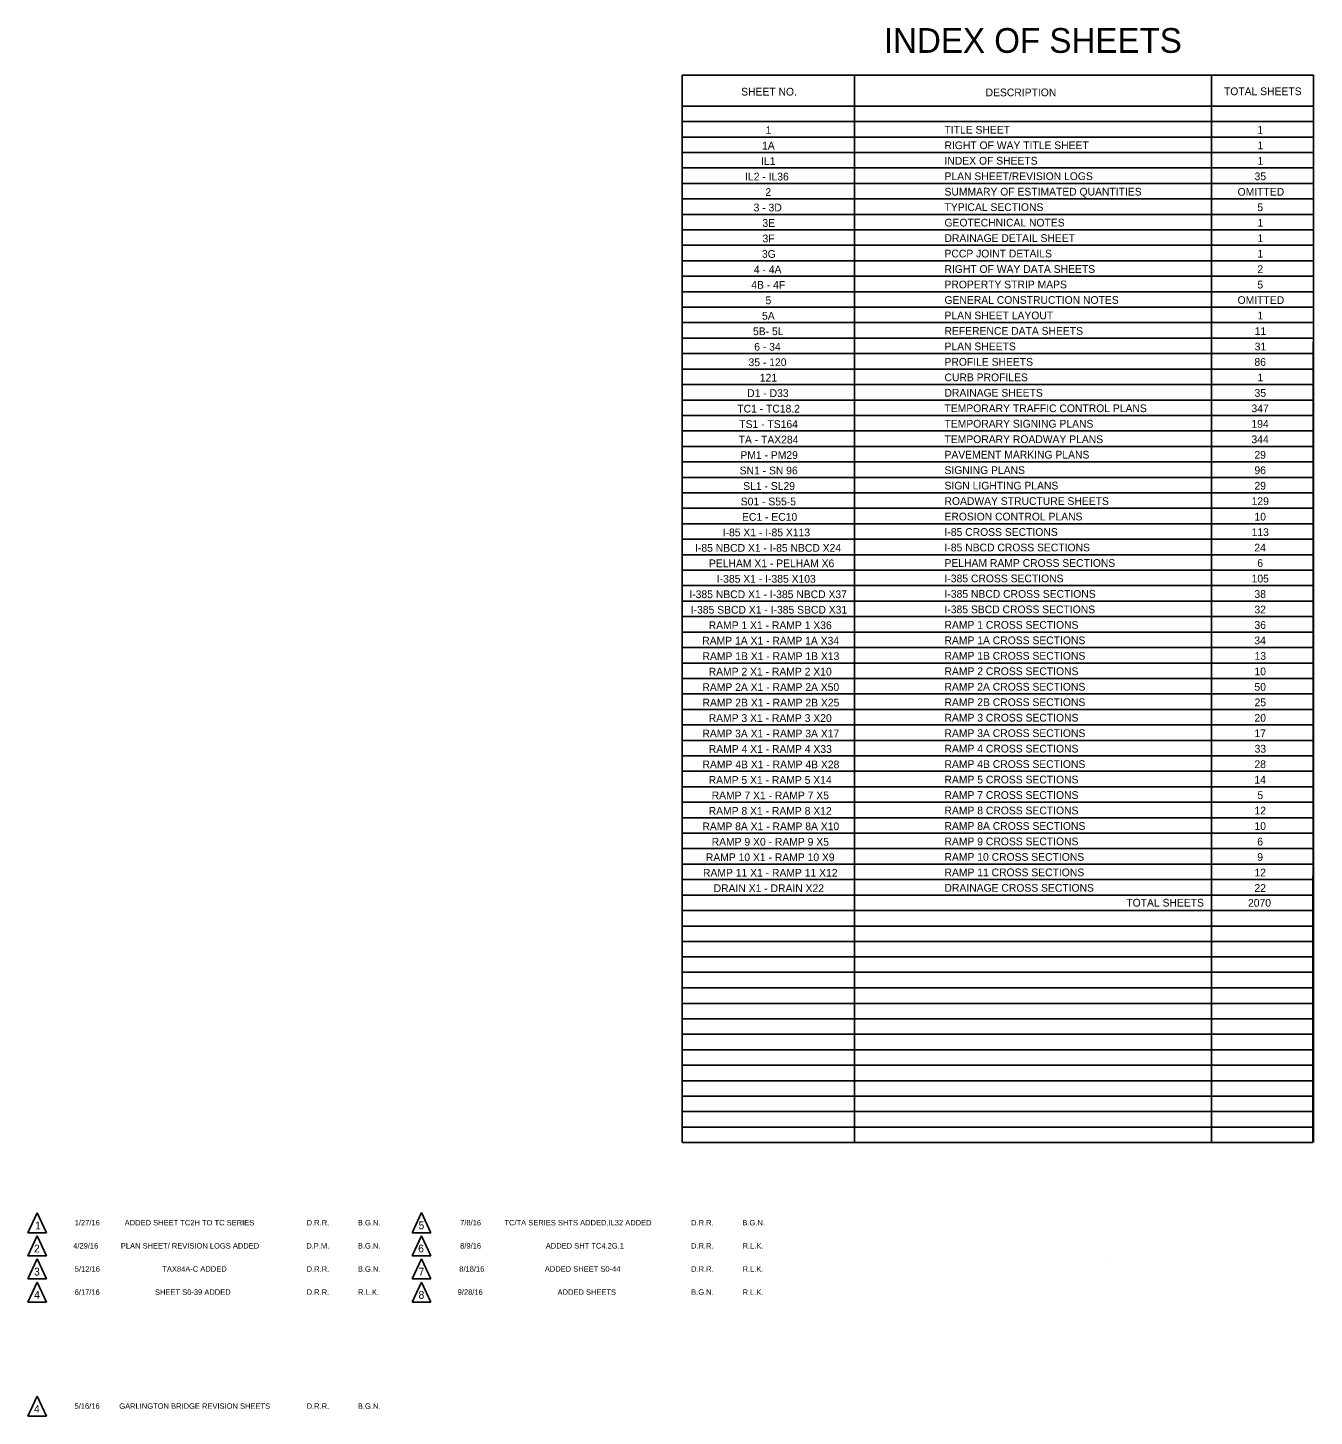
# Model space of a CAD drawing. Extents: x 116 to 2310, y 9 to 1131.
# Drawn here: x 116 to 1155, y 9 to 1131 of the extents above; entities that cross this region are included whole.
import ezdxf

# ---------------------------------------------------------------- set-up
doc = ezdxf.new("R2010")
doc.units = 0
for name, color, linetype in [('BR_AUTO DIMENSION', 7, 'Continuous'), ('BR_TEXT', 7, 'Continuous'), ('Level 3', 7, 'Continuous'), ('Level 6', 7, 'Continuous'), ('RD_SHT_Bndy', 7, 'Continuous'), ('RD_SHT_TX', 7, 'Continuous')]:
    doc.layers.add(name, color=color, linetype=linetype)

msp = doc.modelspace()

# ---------------------------------------------------------------- linework, layer by layer
at = {"layer": 'BR_AUTO DIMENSION'}
for p, q in [((123.7, 173.2), (116.2, 157)), ((123.7, 173.2), (131.2, 157)), ((434.3, 173.3), (426.8, 157.1)), ((434.3, 173.3), (441.8, 157.1)), ((116.2, 157), (131.2, 157)), ((123.7, 154.6), (116.2, 138.4)), ((123.7, 154.6), (131.2, 138.4)), ((426.8, 157.1), (441.8, 157.1)), ((434.3, 154.6), (426.8, 138.4)), ((434.3, 154.6), (441.8, 138.4)), ((116.2, 138.4), (131.2, 138.4)), ((123.7, 135.9), (116.2, 119.7)), ((123.7, 135.9), (131.2, 119.7)), ((426.8, 138.4), (441.8, 138.4)), ((434.3, 135.9), (426.8, 119.7)), ((434.3, 135.9), (441.8, 119.7)), ((116.2, 119.7), (131.2, 119.7)), ((123.7, 117.2), (116.2, 101)), ((123.7, 117.2), (131.2, 101)), ((426.8, 119.7), (441.8, 119.7)), ((434.3, 117.2), (426.8, 101)), ((434.3, 117.2), (441.8, 101)), ((116.2, 101), (131.2, 101)), ((426.8, 101), (441.8, 101)), ((123.7, 25), (116.2, 8.8)), ((123.7, 25), (131.2, 8.8)), ((116.2, 8.8), (131.2, 8.8))]:
    msp.add_line(p, q, dxfattribs=at)
at = {"layer": 'Level 3'}
msp.add_line((987.4, 136), (987.4, 136), dxfattribs=at)
msp.add_line((987.4, 136), (987.4, 136), dxfattribs=at)
at = {"layer": 'RD_SHT_Bndy'}
for p, q in [((644.9, 1092.4), (1154.9, 1092.4)), ((644.9, 1092.4), (644.9, 229.9)), ((784.1, 1092.4), (784.1, 229.9)), ((1072.5, 1092.4), (1072.5, 229.9)), ((1154.9, 1092.4), (1154.3, 229.9)), ((1154.9, 1092.4), (1154.9, 229.9)), ((644.9, 1067.4), (1154.4, 1067.4)), ((645.2, 1054.9), (1154.4, 1054.9)), ((645.2, 1042.4), (1154.4, 1042.4)), ((645.2, 1029.9), (1154.7, 1029.9)), ((645.2, 1017.4), (1154.7, 1017.4)), ((645.2, 1004.9), (1154.7, 1004.9)), ((645.2, 992.4), (1154.4, 992.4)), ((645.2, 979.9), (1154.4, 979.9)), ((645.2, 967.4), (1154.4, 967.4)), ((645.2, 954.9), (1154.7, 954.9)), ((645.2, 942.4), (1154.4, 942.4)), ((645.2, 929.9), (1154.7, 929.9)), ((645.2, 917.4), (1154, 917.4)), ((645.2, 904.9), (1154.2, 904.9)), ((645.2, 892.4), (1154.7, 892.4)), ((645.2, 879.9), (1154.5, 879.9)), ((645.2, 867.4), (1154.7, 867.4)), ((645.2, 854.9), (1154.5, 854.9)), ((645.2, 842.4), (1154.2, 842.4)), ((645.2, 829.9), (1155.5, 829.9)), ((645.2, 817.4), (1154.5, 817.4)), ((645.2, 804.9), (1154.5, 804.9)), ((645.2, 792.4), (1154.5, 792.4)), ((645.2, 779.9), (1154.5, 779.9)), ((645.2, 767.4), (1154.8, 767.4)), ((645.2, 754.9), (1154.5, 754.9)), ((645.2, 742.4), (1154.5, 742.4)), ((645.2, 729.9), (1154.5, 729.9)), ((645.2, 717.4), (1155.3, 717.4)), ((645.2, 704.9), (1154.5, 704.9)), ((645.2, 692.4), (1154.5, 692.4)), ((645.2, 679.9), (1154.8, 679.9)), ((645.2, 667.4), (1154.8, 667.4)), ((645.2, 654.9), (1154.5, 654.9)), ((645.2, 642.4), (1154.3, 642.4)), ((645.2, 629.9), (1154, 629.9)), ((645.2, 617.4), (1154.3, 617.4)), ((645.2, 604.9), (1154.8, 604.9)), ((645.2, 592.4), (1154.7, 592.4)), ((645.2, 579.9), (1154.2, 579.9)), ((645.2, 567.4), (1154, 567.4)), ((645.2, 554.9), (1154.7, 554.9)), ((645.2, 542.4), (1154.5, 542.4)), ((645.2, 529.9), (1154.7, 529.9)), ((645.2, 517.4), (1154.5, 517.4)), ((645.2, 504.9), (1154.7, 504.9)), ((645.2, 492.4), (1154.7, 492.4)), ((645.2, 479.9), (1154.5, 479.9)), ((645.2, 467.4), (1154.5, 467.4)), ((645.2, 454.9), (1154.5, 454.9)), ((645.2, 442.4), (1154.7, 442.4)), ((645.2, 429.9), (1154.7, 429.9)), ((645.2, 417.4), (1154.3, 417.4)), ((645.2, 404.9), (1154.1, 404.9)), ((645.2, 392.4), (1154.1, 392.4)), ((645.2, 379.9), (1154.8, 379.9)), ((645.2, 367.5), (1154.1, 367.5)), ((645.2, 354.9), (1154.1, 354.9)), ((645.2, 342.4), (1154.3, 342.4)), ((645.2, 329.9), (1154.1, 329.9)), ((645.2, 317.4), (1154.3, 317.4)), ((645.2, 304.9), (1154.6, 304.9)), ((645.2, 292.4), (1154.6, 292.4)), ((645.2, 279.9), (1154.3, 279.9)), ((645.2, 267.4), (1154.3, 267.4)), ((645.2, 254.9), (1154.3, 254.9)), ((645.2, 242.4), (1154.3, 242.4)), ((645.2, 229.9), (1154.3, 229.9))]:
    msp.add_line(p, q, dxfattribs=at)

# ---------------------------------------------------------------- texts
at = {"layer": 'BR_TEXT'}
for s, p in [('1', (122.1, 159.8)), ('5', (431.9, 159.9)), ('2', (121.2, 141.2)), ('6', (431.6, 141.2)), ('3', (121.3, 122.5)), ('7', (431.9, 122.5)), ('4', (121.3, 103.8)), ('8', (431.9, 103.7)), ('4', (121.2, 11.6))]:
    msp.add_text(s, height=6.25, dxfattribs=at).set_placement(p)
at = {"layer": 'Level 6'}
msp.add_text('INDEX OF SHEETS', height=20, dxfattribs=at).set_placement((807.8, 1110.4))
at = {"layer": 'RD_SHT_TX'}
for s, height, p in [('SHEET NO.', 6.25, (692.5, 1075.9)), ('DESCRIPTION', 6.25, (890, 1075.3)), ('TOTAL SHEETS', 6.25, (1082.6, 1076.2)), ('1', 6.25, (712.3, 1044.8)), ('TITLE SHEET', 6.25, (856.8, 1045.1)), ('1', 6.25, (1109.7, 1045)), ('1A', 6.25, (709.4, 1032.3)), ('RIGHT OF WAY TITLE SHEET', 6.25, (856.8, 1032.6)), ('1', 6.25, (1109.7, 1032.5)), ('IL1', 6.25, (708.6, 1019.8)), ('INDEX OF SHEETS', 6.25, (856.8, 1020.1)), ('1', 6.25, (1109.7, 1020)), ('IL2 - IL36', 6.25, (695.7, 1007.3)), ('PLAN SHEET/REVISION LOGS', 6.25, (856.8, 1007.6)), ('35', 6.25, (1107.3, 1007.5)), ('2', 6.25, (712.1, 994.8)), ('SUMMARY OF ESTIMATED QUANTITIES', 6.25, (856.8, 995.1)), ('OMITTED', 6.25, (1093.6, 995)), ('3 - 3D', 6.25, (702.6, 982.3)), ('TYPICAL SECTIONS', 6.25, (856.8, 982.6)), ('5', 6.25, (1109.6, 982.5)), ('3E', 6.25, (709.7, 969.8)), ('GEOTECHNICAL NOTES', 6.25, (856.8, 970.1)), ('1', 6.25, (1109.7, 970)), ('3F', 6.25, (709.8, 957.3)), ('DRAINAGE DETAIL SHEET', 6.25, (856.8, 957.6)), ('1', 6.25, (1109.7, 957.5)), ('3G', 6.25, (709.3, 944.8)), ('PCCP JOINT DETAILS', 6.25, (856.8, 945.1)), ('1', 6.25, (1109.7, 945)), ('4 - 4A', 6.25, (702.8, 932.3)), ('RIGHT OF WAY DATA SHEETS', 6.25, (856.8, 932.6)), ('2', 6.25, (1109.6, 932.5)), ('4B - 4F', 6.25, (700.7, 919.8)), ('PROPERTY STRIP MAPS', 6.25, (856.8, 920.1)), ('5', 6.25, (1109.6, 920)), ('5', 6.25, (712.2, 907.3)), ('GENERAL CONSTRUCTION NOTES', 6.25, (856.8, 907.6)), ('OMITTED', 6.25, (1093.6, 907.5)), ('5A', 6.25, (709.4, 894.8)), ('PLAN SHEET LAYOUT', 6.25, (856.8, 895.1)), ('1', 6.25, (1109.7, 895)), ('5B- 5L', 6.25, (702.1, 882.3)), ('REFERENCE DATA SHEETS', 6.25, (856.8, 882.6)), ('11', 6.25, (1107.4, 882.5)), ('6 - 34', 6.25, (703.1, 869.8)), ('PLAN SHEETS', 6.25, (856.8, 870.1)), ('31', 6.25, (1107.4, 870)), ('PROFILE SHEETS', 6.25, (856.8, 857.6)), ('86', 6.25, (1107.2, 857.5)), ('35 - 120', 6.25, (698.5, 857.3)), ('121', 6.25, (707.6, 844.8)), ('CURB PROFILES', 6.25, (856.8, 845.1)), ('1', 6.25, (1109.7, 845)), ('D1 - D33', 6.25, (697.4, 832.3)), ('DRAINAGE SHEETS', 6.25, (856.8, 832.6)), ('35', 6.25, (1107.3, 832.5)), ('TC1 - TC18.2', 6.25, (689.4, 819.8)), ('TEMPORARY TRAFFIC CONTROL PLANS', 6.25, (856.8, 820.1)), ('347', 6.25, (1104.8, 820)), ('TS1 - TS164', 6.25, (691, 807.3)), ('TEMPORARY SIGNING PLANS', 6.25, (856.8, 807.6)), ('194', 6.25, (1104.8, 807.5)), ('TA - TAX284', 6.25, (690.5, 794.8)), ('TEMPORARY ROADWAY PLANS', 6.25, (856.8, 795.1)), ('344', 6.25, (1104.8, 795)), ('PM1 - PM29', 6.25, (691.9, 782.3)), ('PAVEMENT MARKING PLANS', 6.25, (856.8, 782.6)), ('29', 6.25, (1107.2, 782.5)), ('SN1 - SN 96', 6.25, (691.3, 769.8)), ('SIGNING PLANS', 6.25, (856.8, 770.1)), ('96', 6.25, (1107.2, 770)), ('SL1 - SL29', 6.25, (694.2, 757.3)), ('SIGN LIGHTING PLANS', 6.25, (856.8, 757.6)), ('29', 6.25, (1107.2, 757.5)), ('S01 - S55-5', 6.25, (692.2, 744.8)), ('ROADWAY STRUCTURE SHEETS', 6.25, (856.8, 745.1)), ('129', 6.25, (1104.9, 745)), ('EC1 - EC10', 6.25, (693.2, 732.3)), ('EROSION CONTROL PLANS', 6.25, (856.8, 732.6)), ('10', 6.25, (1107.2, 732.5)), ('I-85 X1 - I-85 X113', 6.25, (677.6, 719.8)), ('I-85 CROSS SECTIONS', 6.25, (856.8, 720.1)), ('113', 6.25, (1104.9, 720)), ('I-85 NBCD X1 - I-85 NBCD X24', 6.25, (655.3, 707.3)), ('I-85 NBCD CROSS SECTIONS', 6.25, (856.8, 707.6)), ('24', 6.25, (1107.1, 707.5)), ('PELHAM X1 - PELHAM X6', 6.25, (666.5, 694.8)), ('PELHAM RAMP CROSS SECTIONS', 6.25, (856.8, 695.1)), ('6', 6.25, (1109.5, 695)), ('I-385 X1 - I-385 X103', 6.25, (672.9, 682.3)), ('I-385 CROSS SECTIONS', 6.25, (856.8, 682.6)), ('105', 6.25, (1104.9, 682.5)), ('I-385 NBCD X1 - I-385 NBCD X37', 6.25, (650.7, 669.8)), ('I-385 NBCD CROSS SECTIONS', 6.25, (856.8, 670.1)), ('38', 6.25, (1107.2, 670)), ('I-385 SBCD X1 - I-385 SBCD X31', 6.25, (651.8, 657.3)), ('I-385 SBCD CROSS SECTIONS', 6.25, (856.8, 657.6)), ('32', 6.25, (1107.2, 657.5)), ('RAMP 1 X1 - RAMP 1 X36', 6.25, (666.3, 644.8)), ('RAMP 1 CROSS SECTIONS', 6.25, (856.8, 645.1)), ('36', 6.25, (1107.2, 645)), ('RAMP 1A X1 - RAMP 1A X34', 6.25, (661.1, 632.3)), ('RAMP 1A CROSS SECTIONS', 6.25, (856.8, 632.6)), ('34', 6.25, (1107.1, 632.5)), ('RAMP 1B X1 - RAMP 1B X13', 6.25, (661.3, 619.8)), ('RAMP 1B CROSS SECTIONS', 6.25, (856.8, 620.1)), ('13', 6.25, (1107.3, 620)), ('RAMP 2 X1 - RAMP 2 X10', 6.25, (666.3, 607.3)), ('RAMP 2 CROSS SECTIONS', 6.25, (856.8, 607.6)), ('10', 6.25, (1107.2, 607.5)), ('RAMP 2A X1 - RAMP 2A X50', 6.25, (661.2, 594.8)), ('RAMP 2A CROSS SECTIONS', 6.25, (856.8, 595.1)), ('50', 6.25, (1107.2, 595)), ('RAMP 2B X1 - RAMP 2B X25', 6.25, (661.3, 582.3)), ('RAMP 2B CROSS SECTIONS', 6.25, (856.8, 582.6)), ('25', 6.25, (1107.3, 582.5)), ('RAMP 3 X1 - RAMP 3 X20', 6.25, (666.3, 569.8)), ('RAMP 3 CROSS SECTIONS', 6.25, (856.8, 570.1)), ('20', 6.25, (1107.2, 570)), ('RAMP 3A X1 - RAMP 3A X17', 6.25, (661.2, 557.3)), ('RAMP 3A CROSS SECTIONS', 6.25, (856.8, 557.6)), ('17', 6.25, (1107.2, 557.5)), ('RAMP 4 X1 - RAMP 4 X33', 6.25, (666.4, 544.8)), ('RAMP 4 CROSS SECTIONS', 6.25, (856.8, 545.1)), ('33', 6.25, (1107.3, 545)), ('RAMP 4B X1 - RAMP 4B X28', 6.25, (661.3, 532.3)), ('RAMP 4B CROSS SECTIONS', 6.25, (856.8, 532.6)), ('28', 6.25, (1107.2, 532.5)), ('RAMP 5 X1 - RAMP 5 X14', 6.25, (666.3, 519.8)), ('RAMP 5 CROSS SECTIONS', 6.25, (856.8, 520.1)), ('14', 6.25, (1107.1, 520)), ('RAMP 7 X1 - RAMP 7 X5', 6.25, (668.7, 507.3)), ('RAMP 7 CROSS SECTIONS', 6.25, (856.8, 507.6)), ('5', 6.25, (1109.6, 507.5)), ('RAMP 8 X1 - RAMP 8 X12', 6.25, (666.3, 494.8)), ('RAMP 8 CROSS SECTIONS', 6.25, (856.8, 495.1)), ('12', 6.25, (1107.2, 495)), ('RAMP 8A X1 - RAMP 8A X10', 6.25, (661.2, 482.3)), ('RAMP 8A CROSS SECTIONS', 6.25, (856.8, 482.6)), ('10', 6.25, (1107.2, 482.5)), ('RAMP 9 X0 - RAMP 9 X5', 6.25, (668.7, 469.8)), ('RAMP 9 CROSS SECTIONS', 6.25, (856.8, 470.1)), ('6', 6.25, (1109.5, 470)), ('RAMP 10 X1 - RAMP 10 X9', 6.25, (664, 457.3)), ('RAMP 10 CROSS SECTIONS', 6.25, (856.8, 457.6)), ('9', 6.25, (1109.5, 457.5)), ('RAMP 11 X1 - RAMP 11 X12', 6.25, (661.7, 444.8)), ('RAMP 11 CROSS SECTIONS', 6.25, (856.8, 445.1)), ('12', 6.25, (1107.2, 445)), ('DRAIN X1 - DRAIN X22', 6.25, (670.3, 432.3)), ('DRAINAGE CROSS SECTIONS', 6.25, (856.8, 432.6)), ('22', 6.25, (1107.2, 432.5)), ('TOTAL SHEETS', 6.25, (1003.7, 420.6)), ('2070', 6.25, (1102, 420.5)), ('1/27/16', 4.4, (154.1, 163)), ('ADDED SHEET TC2H TO TC SERIES', 4.4, (194.5, 163)), ('D.R.R.', 4.4, (341.5, 163)), ('B.G.N.', 4.4, (382.9, 163)), ('7/8/16', 4.4, (465.5, 163)), ('TC/TA SERIES SHTS ADDED,IL32 ADDED', 4.4, (501.3, 163)), ('D.R.R.', 4.4, (652.1, 163)), ('B.G.N.', 4.4, (693.5, 163)), ('4/29/16', 4.4, (152.9, 144.3)), ('PLAN SHEET/ REVISION LOGS ADDED', 4.4, (191.4, 144.3)), ('D.P.M.', 4.4, (341.2, 144.3)), ('B.G.N.', 4.4, (382.9, 144.3)), ('8/9/16', 4.4, (465.5, 144.3)), ('ADDED SHT TC4.2G.1', 4.4, (534.7, 144.3)), ('D.R.R.', 4.4, (652.1, 144.3)), ('R.L.K.', 4.4, (693.7, 144.3)), ('5/12/16', 4.4, (154.2, 125.6)), ('TAX84A-C ADDED', 4.4, (224.9, 125.6)), ('D.R.R.', 4.4, (341.5, 125.6)), ('B.G.N.', 4.4, (382.9, 125.6)), ('8/18/16', 4.4, (464.8, 125.6)), ('ADDED SHEET S0-44', 4.4, (533.9, 125.6)), ('D.R.R.', 4.4, (652.1, 125.6)), ('R.L.K.', 4.4, (693.7, 125.6)), ('6/17/16', 4.4, (154.1, 106.9)), ('SHEET S0-39 ADDED', 4.4, (219, 106.9)), ('D.R.R.', 4.4, (341.5, 106.9)), ('R.L.K.', 4.4, (383.1, 106.9)), ('9/28/16', 4.4, (463.5, 106.9)), ('ADDED SHEETS', 4.4, (544.2, 106.9)), ('B.G.N.', 4.4, (652.1, 106.9)), ('R.L.K.', 4.4, (693.7, 106.9)), ('5/16/16', 4.4, (154, 14.8)), ('GARLINGTON BRIDGE REVISION SHEETS', 4.4, (190.1, 14.8)), ('D.R.R.', 4.4, (341.5, 14.8)), ('B.G.N.', 4.4, (382.9, 14.8))]:
    msp.add_text(s, height=height, dxfattribs=at).set_placement(p)

doc.saveas('drawing.dxf')
